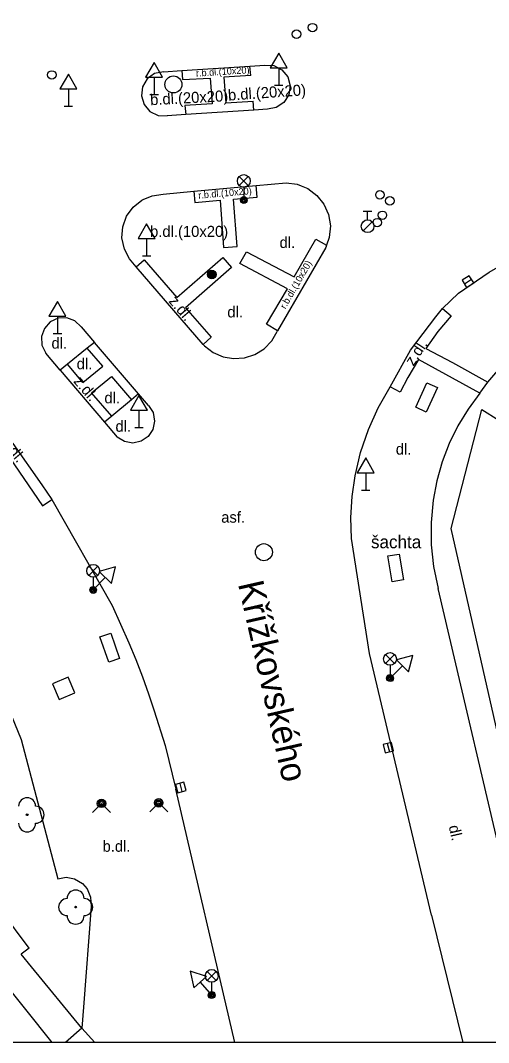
# Model space of a CAD drawing. Extents: x -600309 to -598967, y -1161267 to -1160292.
# Drawn here: x -599727.7 to -599700.2, y -1161267 to -1161207 of the extents above; entities that cross this region are included whole.
import ezdxf

# ---------------------------------------------------------------- set-up
doc = ezdxf.new("R2010")
doc.units = 0
for name, color, linetype in [('Level 10', 7, 'Continuous'), ('Level 11', 7, 'Continuous'), ('Level 13', 7, 'Continuous'), ('Level 21', 7, 'Continuous'), ('Level 22', 7, 'Continuous'), ('Level 25', 7, 'Continuous'), ('Level 26', 7, 'Continuous'), ('Level 27', 7, 'Continuous'), ('Level 28', 7, 'Continuous'), ('Level 31', 7, 'Continuous'), ('Level 33', 7, 'Continuous'), ('Level 34', 7, 'Continuous'), ('Level 40', 7, 'Continuous'), ('Level 42', 7, 'Continuous'), ('Level 49', 7, 'Continuous'), ('Vrstva 63', 7, 'Continuous')]:
    doc.layers.add(name, color=color, linetype=linetype)

msp = doc.modelspace()

# ---------------------------------------------------------------- linework, layer by layer
at = {"layer": 'Level 10'}
for p, q in [((-599715.1282, -1161267.0314), (-599718.6, -1161252.15)), ((-599703.58, -1161259.55), (-599701.728, -1161267.0314))]:
    msp.add_line(p, q, dxfattribs=at)
for points in [[(-599714.24, -1161209.7), (-599713.37, -1161209.64)], [(-599714.19, -1161210.26), (-599714.24, -1161209.7)], [(-599713.37, -1161209.64), (-599712.84, -1161209.67), (-599712.36, -1161209.92), (-599712.02, -1161210.33), (-599711.88, -1161210.85), (-599711.96, -1161211.38), (-599712.24, -1161211.83), (-599712.69, -1161212.13), (-599713.21, -1161212.23)], [(-599719.31, -1161210.03), (-599719.84, -1161210.14), (-599720.27, -1161210.45), (-599720.55, -1161210.9099), (-599720.62, -1161211.44), (-599720.46, -1161211.95), (-599720.12, -1161212.36), (-599719.64, -1161212.6), (-599719.1, -1161212.62)], [(-599719.31, -1161210.03), (-599718.25, -1161209.96)], [(-599718.25, -1161209.96), (-599718.2, -1161210.48)], [(-599718.06, -1161212.02), (-599718.01, -1161212.55)], [(-599714.02, -1161212.28), (-599714.06, -1161211.76)], [(-599718.01, -1161212.55), (-599719.1, -1161212.62)], [(-599713.21, -1161212.23), (-599714.02, -1161212.28)], [(-599717.53, -1161217.05), (-599713.88, -1161216.71)], [(-599713.88, -1161216.71), (-599712.12, -1161216.55)], [(-599712.12, -1161216.55), (-599711.46, -1161216.64), (-599711.23, -1161216.73), (-599710.84, -1161216.89), (-599710.31, -1161217.29), (-599709.89, -1161217.81), (-599709.62, -1161218.4099), (-599709.51, -1161219.07), (-599709.59, -1161219.77), (-599709.74, -1161220.2199)], [(-599721.32, -1161221.02), (-599721.62, -1161220.44), (-599721.76, -1161219.79), (-599721.71, -1161219.14), (-599721.49, -1161218.51), (-599721.11, -1161217.98), (-599720.6, -1161217.57), (-599720.51, -1161217.53), (-599719.99, -1161217.31), (-599719.34, -1161217.2199)], [(-599719.34, -1161217.2199), (-599717.53, -1161217.05)], [(-599701.98, -1161223.04), (-599700.18, -1161221.79), (-599698.28, -1161220.71), (-599696.28, -1161219.82), (-599694.37, -1161219.17), (-599692.41, -1161218.68)], [(-599709.79, -1161220.36), (-599712.62, -1161225.25)], [(-599709.74, -1161220.2199), (-599709.79, -1161220.36)], [(-599720.93, -1161221.48), (-599721.32, -1161221.02)], [(-599716.98, -1161226.04), (-599720.93, -1161221.48)], [(-599736.18, -1161223.34), (-599735.7, -1161223.78), (-599731.39, -1161228.07), (-599728.17, -1161231.85), (-599726.46, -1161234.28), (-599725.88, -1161235.14)], [(-599702.92, -1161223.93), (-599701.98, -1161223.04)], [(-599706.01, -1161228.53), (-599704.8, -1161226.37), (-599703.31, -1161224.42), (-599702.92, -1161223.93)], [(-599724.15, -1161225.01), (-599724.52, -1161224.6599), (-599725, -1161224.49), (-599725.51, -1161224.51), (-599725.9699, -1161224.7199), (-599726.32, -1161225.1), (-599726.49, -1161225.58), (-599726.46, -1161226.09), (-599726.24, -1161226.55)], [(-599724.15, -1161225.01), (-599723.38, -1161225.92)], [(-599716.91, -1161226.12), (-599716.41, -1161226.51), (-599715.82, -1161226.77), (-599715.2, -1161226.87), (-599714.56, -1161226.83), (-599713.95, -1161226.63), (-599713.41, -1161226.3), (-599712.96, -1161225.84), (-599712.64, -1161225.29)], [(-599712.62, -1161225.25), (-599712.64, -1161225.29)], [(-599723.38, -1161225.92), (-599723.8, -1161226.26)], [(-599723.8, -1161226.26), (-599724.96, -1161227.2)], [(-599716.9099, -1161226.12), (-599716.98, -1161226.04)], [(-599725.39, -1161227.55), (-599726.24, -1161226.55)], [(-599724.96, -1161227.2), (-599725.39, -1161227.55)], [(-599708.28, -1161237.44), (-599708.31, -1161236.21), (-599708.24, -1161234.97), (-599708.06, -1161233.75), (-599707.74, -1161232.38), (-599707.28, -1161231.04), (-599706.71, -1161229.76), (-599706.01, -1161228.53)], [(-599721.2, -1161229.3), (-599722.35, -1161230.25)], [(-599720.78, -1161228.95), (-599721.2, -1161229.3)], [(-599720.2, -1161229.62), (-599720.78, -1161228.95)], [(-599720.2, -1161229.62), (-599719.93, -1161230.04), (-599719.84, -1161230.54), (-599719.94, -1161231.03), (-599720.2199, -1161231.45), (-599720.64, -1161231.73), (-599721.13, -1161231.84), (-599721.62, -1161231.75), (-599722.05, -1161231.48)], [(-599722.35, -1161230.25), (-599722.79, -1161230.61)], [(-599722.79, -1161230.61), (-599722.05, -1161231.48)], [(-599725.88, -1161235.14), (-599722.34, -1161241.38)], [(-599703.58, -1161259.55), (-599707.22, -1161244.18), (-599708.28, -1161237.44)], [(-599722.34, -1161241.38), (-599721.35, -1161243.57)], [(-599721.35, -1161243.57), (-599720.95, -1161244.55), (-599720.56, -1161245.55), (-599720.2, -1161246.55), (-599719.86, -1161247.55)], [(-599719.86, -1161247.55), (-599719.23, -1161249.59)], [(-599719.23, -1161249.59), (-599718.6, -1161252.15)]]:
    msp.add_lwpolyline(points, dxfattribs=at)
at = {"layer": 'Level 11'}
for p, q in [((-599724.11, -1161266.18), (-599725.086, -1161267.0314)), ((-599723.3461, -1161267.0314), (-599724.11, -1161266.18))]:
    msp.add_line(p, q, dxfattribs=at)
for points in [[(-599718.25, -1161209.96), (-599714.24, -1161209.7)], [(-599714.19, -1161210.26), (-599715.78, -1161210.36), (-599715.65, -1161211.86), (-599714.06, -1161211.76)], [(-599718.2, -1161210.48), (-599716.57, -1161210.4), (-599716.45, -1161211.9099), (-599718.06, -1161212.02)], [(-599714.02, -1161212.28), (-599718.01, -1161212.55)], [(-599713.82, -1161217.39), (-599713.88, -1161216.71)], [(-599717.53, -1161217.05), (-599717.4699, -1161217.71)], [(-599715.2, -1161217.52), (-599713.82, -1161217.39)], [(-599715, -1161220.29), (-599715.2, -1161217.52)], [(-599717.4699, -1161217.71), (-599715.99, -1161217.58)], [(-599715.99, -1161217.58), (-599715.79, -1161220.36)], [(-599711.65, -1161222.08), (-599710.37, -1161219.86)], [(-599710.37, -1161219.86), (-599709.74, -1161220.2199)], [(-599715.79, -1161220.36), (-599715, -1161220.29)], [(-599720.93, -1161221.48), (-599720.45, -1161221.07)], [(-599720.45, -1161221.07), (-599718.54, -1161223.29)], [(-599718.54, -1161223.29), (-599715.84, -1161220.93)], [(-599715.84, -1161220.93), (-599715.32, -1161221.52)], [(-599714.83, -1161221.29), (-599714.44, -1161220.61)], [(-599714.44, -1161220.61), (-599711.65, -1161222.08)], [(-599715.32, -1161221.52), (-599718.02, -1161223.9)], [(-599712.04, -1161222.78), (-599714.83, -1161221.29)], [(-599713.26, -1161224.86), (-599712.04, -1161222.78)], [(-599718.02, -1161223.9), (-599716.51, -1161225.62)], [(-599702.92, -1161223.93), (-599702.42, -1161224.36), (-599703.2, -1161225.29), (-599703.9, -1161226.28), (-599702.33, -1161227.11), (-599700.26, -1161228.26)], [(-599700.26, -1161228.26), (-599699.45, -1161227.29), (-599698.54, -1161226.42), (-599697.55, -1161225.64), (-599696.67, -1161225.07), (-599695.74, -1161224.59), (-599694.78, -1161224.18), (-599693.78, -1161223.86), (-599692.76, -1161223.62)], [(-599712.62, -1161225.25), (-599713.26, -1161224.86)], [(-599720.78, -1161228.95), (-599723.38, -1161225.92)], [(-599716.51, -1161225.62), (-599716.98, -1161226.04)], [(-599724.05, -1161228.27), (-599722.88, -1161227.32), (-599723.8, -1161226.26)], [(-599700.73, -1161228.9099), (-599704.33, -1161226.93), (-599704.96, -1161227.99), (-599705.42, -1161228.85), (-599706.01, -1161228.53)], [(-599725.39, -1161227.55), (-599722.79, -1161230.61)], [(-599724.05, -1161228.27), (-599724.96, -1161227.2)], [(-599723.54, -1161228.89), (-599722.37, -1161227.93)], [(-599722.37, -1161227.93), (-599721.2, -1161229.3)], [(-599704.49, -1161229.73), (-599703.85, -1161228.3), (-599703.23, -1161228.57), (-599703.89, -1161230.02), (-599704.49, -1161229.73)], [(-599700.73, -1161228.9099), (-599700.26, -1161228.26)], [(-599722.35, -1161230.25), (-599723.54, -1161228.89)], [(-599700.73, -1161228.91), (-599701.42, -1161229.84), (-599702.02, -1161230.83), (-599702.53, -1161231.86), (-599702.94, -1161232.94), (-599703.26, -1161234.05), (-599703.48, -1161235.19), (-599703.6, -1161236.49), (-599703.59, -1161237.8), (-599703.45, -1161239.09), (-599703.18, -1161240.37)], [(-599728.45, -1161232.55), (-599728.07, -1161233.11), (-599726.43, -1161235.51)], [(-599726.43, -1161235.51), (-599725.88, -1161235.14)], [(-599734.35, -1161236.94), (-599733.14, -1161238.57), (-599732.62, -1161239.4099), (-599731.7, -1161240.96), (-599730.07, -1161243.74), (-599729.62, -1161244.59), (-599728.07, -1161248.28), (-599727.69, -1161249.23), (-599725.53, -1161257.4099), (-599725.03, -1161257.33), (-599724.55, -1161257.42), (-599724.08, -1161257.69), (-599723.8, -1161258), (-599723.6, -1161258.5), (-599723.57, -1161259.04), (-599724.0163, -1161264.9439), (-599724.11, -1161266.18)], [(-599706.14, -1161238.46), (-599705.4699, -1161238.35), (-599705.2199, -1161239.87), (-599705.89, -1161239.98), (-599706.14, -1161238.46)], [(-599696.91, -1161267.0314), (-599698.9, -1161258.65), (-599703.18, -1161240.37)], [(-599722.4099, -1161243), (-599721.9, -1161244.48), (-599722.54, -1161244.7), (-599723.05, -1161243.2199), (-599722.4099, -1161243)], [(-599727.2199, -1161261.49), (-599728.88, -1161259.26)], [(-599727.2199, -1161261.49), (-599727.69, -1161261.84)], [(-599724.11, -1161266.18), (-599727.0742, -1161262.5862), (-599727.69, -1161261.84)]]:
    msp.add_lwpolyline(points, dxfattribs=at)
at = {"layer": 'Level 13'}
msp.add_line((-599733.82, -1161257.15), (-599725.8784, -1161267.0314), dxfattribs=at)
at = {"layer": 'Level 21'}
msp.add_lwpolyline([(-599694.74, -1161247.97), (-599699.28, -1161250.64), (-599702.42, -1161236.85), (-599700.62, -1161229.86), (-599696.63, -1161232.37)], dxfattribs=at)
at = {"layer": 'Level 22'}
for centre in [(-599727.33, -1161253.6599), (-599724.48, -1161259.08)]:
    msp.add_circle(centre, 0.05, dxfattribs=at)
for centre, start, end in [((-599727.33, -1161253.1599), 0, 180), ((-599726.83, -1161253.6599), 270, 90), ((-599727.33, -1161254.1599), 180, 0), ((-599724.48, -1161258.58), 0, 180), ((-599724.98, -1161259.08), 90, 270), ((-599723.98, -1161259.08), 270, 90), ((-599724.48, -1161259.58), 180, 0)]:
    msp.add_arc(centre, 0.5, start, end, dxfattribs=at)
at = {"layer": 'Level 25'}
for radius in [0.25, 0.2, 0.15, 0.1, 0.05]:
    msp.add_circle((-599716.48, -1161221.94), radius, dxfattribs=at)
at = {"layer": 'Level 26'}
msp.add_lwpolyline([(-599725.8444, -1161245.9621), (-599725.4579, -1161246.8844), (-599724.5356, -1161246.4979), (-599724.9221, -1161245.5756)], close=True, dxfattribs=at)
at = {"layer": 'Level 27'}
for p, q in [((-599701.6411, -1161222.4839), (-599701.2189, -1161222.2161)), ((-599706.1721, -1161249.4777), (-599706.0479, -1161249.9621)), ((-599718.3678, -1161251.8194), (-599718.2322, -1161252.3006))]:
    msp.add_line(p, q, dxfattribs=at)
for points in [[(-599701.5072, -1161222.695), (-599701.085, -1161222.4272), (-599701.3528, -1161222.005), (-599701.775, -1161222.2728)], [(-599706.4143, -1161249.5398), (-599706.2901, -1161250.0242), (-599705.8057, -1161249.9), (-599705.9299, -1161249.4156)], [(-599718.6084, -1161251.8872), (-599718.4728, -1161252.3684), (-599717.9916, -1161252.2328), (-599718.1272, -1161251.7516)]]:
    msp.add_lwpolyline(points, close=True, dxfattribs=at)
for centre in [(-599718.74, -1161210.78), (-599713.42, -1161238.24)]:
    msp.add_circle(centre, 0.5, dxfattribs=at)
at = {"layer": 'Level 28'}
for p, q in [((-599707.58, -1161218.225), (-599707.08, -1161218.225)), ((-599707.33, -1161218.725), (-599707.33, -1161218.225)), ((-599707.588, -1161219.372), (-599707.058, -1161218.842))]:
    msp.add_line(p, q, dxfattribs=at)
for centre, radius in [((-599710.56, -1161207.44), 0.25), ((-599711.5, -1161207.83), 0.25), ((-599725.88, -1161210.2199), 0.25), ((-599706.6, -1161217.26), 0.25), ((-599706.02, -1161217.61), 0.25), ((-599706.76, -1161218.89), 0.25), ((-599706.46, -1161218.46), 0.25), ((-599707.33, -1161219.1), 0.375)]:
    msp.add_circle(centre, radius, dxfattribs=at)
at = {"layer": 'Level 31'}
for points in [[(-599723.49, -1161253.52), (-599722.96, -1161252.99), (-599722.43, -1161253.52)], [(-599720.13, -1161253.49), (-599719.6, -1161252.96), (-599719.07, -1161253.49)]]:
    msp.add_lwpolyline(points, dxfattribs=at)
for centre, radius in [((-599722.96, -1161252.99), 0.25), ((-599722.96, -1161252.99), 0.18), ((-599722.96, -1161252.99), 0.11), ((-599719.6, -1161252.96), 0.25), ((-599719.6, -1161252.96), 0.18), ((-599719.6, -1161252.96), 0.11)]:
    msp.add_circle(centre, radius, dxfattribs=at)
at = {"layer": 'Level 33'}
for p, q in [((-599714.865, -1161216.71), (-599714.335, -1161216.18)), ((-599714.865, -1161216.18), (-599714.335, -1161216.71)), ((-599714.6, -1161216.82), (-599714.6, -1161217.57)), ((-599723.715, -1161239.6), (-599723.185, -1161239.07)), ((-599723.715, -1161239.07), (-599723.185, -1161239.6)), ((-599723.45, -1161239.71), (-599723.45, -1161240.46)), ((-599706.275, -1161244.77), (-599705.745, -1161244.24)), ((-599706.275, -1161244.24), (-599705.745, -1161244.77)), ((-599706.01, -1161244.88), (-599706.01, -1161245.63)), ((-599716.755, -1161263.38), (-599716.225, -1161262.85)), ((-599716.755, -1161262.85), (-599716.225, -1161263.38)), ((-599716.49, -1161263.49), (-599716.49, -1161264.24))]:
    msp.add_line(p, q, dxfattribs=at)
for centre, radius in [((-599714.6, -1161216.445), 0.375), ((-599714.6, -1161217.57), 0.2), ((-599714.6, -1161217.57), 0.1445), ((-599714.6, -1161217.57), 0.0876), ((-599723.45, -1161239.335), 0.375), ((-599723.45, -1161240.46), 0.2), ((-599723.45, -1161240.46), 0.1445), ((-599723.45, -1161240.46), 0.0876), ((-599706.01, -1161244.505), 0.375), ((-599706.01, -1161245.63), 0.2), ((-599706.01, -1161245.63), 0.1445), ((-599706.01, -1161245.63), 0.0876), ((-599716.49, -1161263.115), 0.375), ((-599716.49, -1161264.24), 0.2), ((-599716.49, -1161264.24), 0.1445), ((-599716.49, -1161264.24), 0.0876)]:
    msp.add_circle(centre, radius, dxfattribs=at)
at = {"layer": 'Level 34'}
for p, q in [((-599712.55, -1161209.802), (-599712.55, -1161210.82)), ((-599719.87, -1161210.352), (-599719.87, -1161211.37)), ((-599712.8, -1161210.82), (-599712.3, -1161210.82)), ((-599724.9099, -1161211.042), (-599724.9099, -1161212.06)), ((-599720.12, -1161211.37), (-599719.62, -1161211.37)), ((-599725.1599, -1161212.06), (-599724.6599, -1161212.06)), ((-599720.31, -1161219.832), (-599720.31, -1161220.85)), ((-599720.56, -1161220.85), (-599720.06, -1161220.85)), ((-599725.55, -1161224.3919), (-599725.55, -1161225.4099)), ((-599725.8, -1161225.4099), (-599725.3, -1161225.4099)), ((-599720.76, -1161229.902), (-599720.76, -1161230.92)), ((-599721.01, -1161230.92), (-599720.51, -1161230.92)), ((-599707.44, -1161233.572), (-599707.44, -1161234.59)), ((-599707.69, -1161234.59), (-599707.19, -1161234.59)), ((-599723.6297, -1161240.2862), (-599723.2703, -1161240.6338)), ((-599722.7425, -1161239.7281), (-599723.45, -1161240.46)), ((-599705.2829, -1161244.9175), (-599706.01, -1161245.63)), ((-599706.185, -1161245.4514), (-599705.835, -1161245.8086)), ((-599717.1722, -1161263.4844), (-599716.49, -1161264.24)), ((-599716.6756, -1161264.4075), (-599716.3044, -1161264.0725))]:
    msp.add_line(p, q, dxfattribs=at)
for points in [[(-599713.05, -1161209.802), (-599712.05, -1161209.802), (-599712.55, -1161208.936)], [(-599720.37, -1161210.352), (-599719.37, -1161210.352), (-599719.87, -1161209.486)], [(-599725.4099, -1161211.042), (-599724.4099, -1161211.042), (-599724.9099, -1161210.176)], [(-599720.81, -1161219.832), (-599719.81, -1161219.832), (-599720.31, -1161218.966)], [(-599726.05, -1161224.3919), (-599725.05, -1161224.3919), (-599725.55, -1161223.5259)], [(-599721.26, -1161229.902), (-599720.26, -1161229.902), (-599720.76, -1161229.036)], [(-599707.94, -1161233.572), (-599706.94, -1161233.572), (-599707.44, -1161232.706)], [(-599723.1019, -1161239.3806), (-599722.383, -1161240.0756), (-599722.1406, -1161239.1054)], [(-599705.6329, -1161244.5604), (-599704.933, -1161245.2746), (-599704.6644, -1161244.3114)], [(-599717.5433, -1161263.8195), (-599716.8011, -1161263.1493), (-599717.7526, -1161262.8417)]]:
    msp.add_lwpolyline(points, close=True, dxfattribs=at)
at = {"layer": 'Vrstva 63'}
msp.add_lwpolyline([(-600308.541, -1160292.3474), (-598967.1085, -1160292.3474), (-598967.1085, -1161267.0314), (-600308.541, -1161267.0314)], close=True, dxfattribs=at)

# ---------------------------------------------------------------- texts
at = {"layer": 'Level 40'}
for s, height, rotation, p in [('r.b.dl.(10x20)', 0.4, 3.647867, (-599717.4, -1161210.32)), ('b.dl.(20x20)', 0.65, 4, (-599715.51, -1161211.73)), ('b.dl.(20x20)', 0.65, 3, (-599720.09, -1161212)), ('r.b.dl.(10x20)', 0.4, 4.996028, (-599717.26, -1161217.49)), ('r.b.dl.(10x20)', 0.4, 60.017675, (-599712.16, -1161223.99)), ('z.dl.', 0.65, 310.52, (-599719.05, -1161223.52)), ('z.dl.', 0.65, 56.74, (-599704.64, -1161227.35)), ('z.dl.', 0.65, 310.52, (-599724.64, -1161228.23)), ('z.dl.', 0.65, 310.52, (-599728.92, -1161231.83)), ('dl.', 0.65, 283, (-599702.57, -1161254.34))]:
    msp.add_text(s, height=height, rotation=rotation, dxfattribs=at).set_placement(p)
for s, p in [('b.dl.(10x20)', (-599720.11, -1161219.73)), ('dl.', (-599712.5, -1161220.38)), (' dl.', (-599715.81, -1161224.46)), ('dl.', (-599725.9, -1161226.29)), ('dl.', (-599724.42, -1161227.5)), ('dl.', (-599722.79, -1161229.5)), ('dl.', (-599722.14, -1161231.17)), ('dl.', (-599705.67, -1161232.51)), ('asf.', (-599715.93, -1161236.51)), ('b.dl.', (-599722.9, -1161255.83))]:
    msp.add_text(s, height=0.65, dxfattribs=at).set_placement(p)
at = {"layer": 'Level 42'}
msp.add_text('šachta', height=0.75, dxfattribs=at).set_placement((-599707.13, -1161238.01))
at = {"layer": 'Level 49'}
msp.add_text('Křížkovského', height=1.5, rotation=282.76, dxfattribs=at).set_placement((-599714.95, -1161240.09))

doc.saveas('drawing.dxf')
